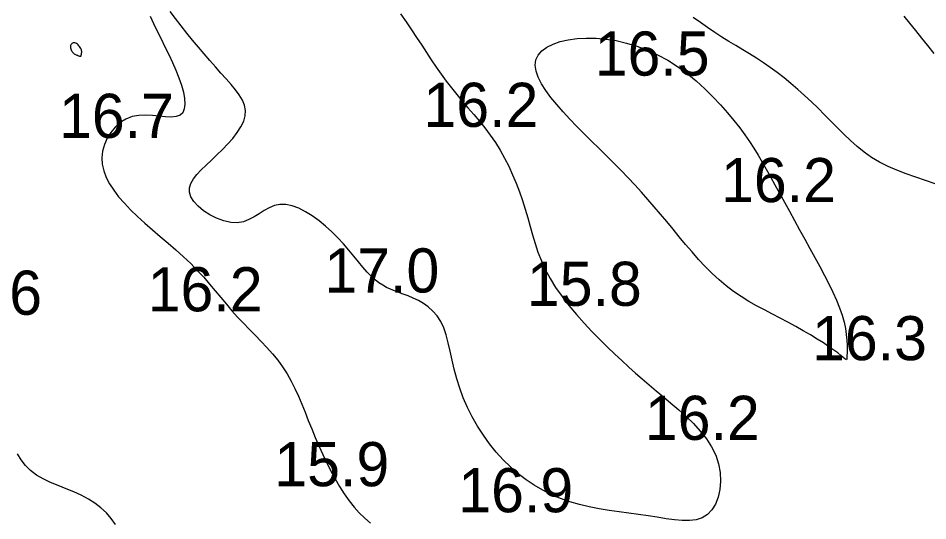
# Model space of a CAD drawing. Extents: x 3040093 to 3056816, y 408076 to 509144.
# Drawn here: x 3045566.4 to 3045669.4, y 434050.9 to 434107.9 of the extents above; entities that cross this region are included whole.
import ezdxf

# ---------------------------------------------------------------- set-up
doc = ezdxf.new("R2010")
doc.units = 0
doc.layers.add('V-CHAN-CONT-EL17', color=7, linetype='Continuous')
doc.layers.add('V-TOPO-SOUN-0610', color=7, linetype='Continuous')

msp = doc.modelspace()

# ---------------------------------------------------------------- linework, layer by layer
at = {"layer": 'V-CHAN-CONT-EL17'}
for points in [[(3045609.73, 434108.38), (3045610.36, 434107.48), (3045610.97, 434106.58), (3045611.55, 434105.7), (3045612.12, 434104.84), (3045612.67, 434103.99), (3045613.21, 434103.16), (3045613.76, 434102.34), (3045614.32, 434101.54), (3045614.89, 434100.76), (3045615.48, 434099.98), (3045616.09, 434099.23), (3045616.72, 434098.48), (3045617.36, 434097.74), (3045618.01, 434096.99), (3045618.65, 434096.23), (3045619.27, 434095.45), (3045619.88, 434094.64), (3045620.46, 434093.81), (3045621, 434092.94), (3045621.51, 434092.04), (3045621.98, 434091.1), (3045622.42, 434090.15), (3045622.83, 434089.19), (3045623.2, 434088.21), (3045623.54, 434087.23), (3045623.85, 434086.25), (3045624.13, 434085.27), (3045624.4, 434084.3), (3045624.67, 434083.32), (3045624.96, 434082.35), (3045625.29, 434081.37), (3045625.67, 434080.39), (3045626.12, 434079.39), (3045626.65, 434078.39), (3045627.29, 434077.37), (3045628.01, 434076.35), (3045628.8, 434075.33), (3045629.64, 434074.32), (3045630.51, 434073.34), (3045631.4, 434072.39), (3045632.28, 434071.48), (3045633.15, 434070.62), (3045633.98, 434069.83), (3045634.78, 434069.08), (3045635.56, 434068.36), (3045636.33, 434067.68), (3045637.1, 434067.01), (3045637.88, 434066.34), (3045638.68, 434065.67), (3045639.5, 434064.98), (3045640.35, 434064.27), (3045641.22, 434063.52), (3045642.08, 434062.75), (3045642.9, 434061.94), (3045643.67, 434061.1), (3045644.36, 434060.22), (3045644.95, 434059.31), (3045645.41, 434058.36), (3045645.74, 434057.38), (3045645.92, 434056.39), (3045645.97, 434055.41), (3045645.9, 434054.48), (3045645.71, 434053.6), (3045645.4, 434052.82), (3045644.99, 434052.16), (3045644.49, 434051.63), (3045643.89, 434051.27), (3045643.21, 434051.05), (3045642.45, 434050.96), (3045641.62, 434050.96), (3045640.73, 434051.04), (3045639.79, 434051.17), (3045638.79, 434051.33), (3045637.75, 434051.49), (3045636.68, 434051.65), (3045635.58, 434051.79), (3045634.47, 434051.94), (3045633.34, 434052.1), (3045632.21, 434052.29), (3045631.09, 434052.51), (3045629.98, 434052.77), (3045628.9, 434053.08), (3045627.84, 434053.46), (3045626.81, 434053.89), (3045625.82, 434054.39), (3045624.86, 434054.96), (3045623.94, 434055.58), (3045623.04, 434056.27), (3045622.18, 434057.03), (3045621.35, 434057.84), (3045620.56, 434058.72), (3045619.81, 434059.66), (3045619.11, 434060.64), (3045618.45, 434061.65), (3045617.85, 434062.7), (3045617.31, 434063.78), (3045616.83, 434064.86), (3045616.43, 434065.95), (3045616.09, 434067.03), (3045615.81, 434068.1), (3045615.57, 434069.15), (3045615.35, 434070.15), (3045615.13, 434071.1), (3045614.89, 434071.99), (3045614.61, 434072.8), (3045614.27, 434073.53), (3045613.86, 434074.16), (3045613.39, 434074.7), (3045612.87, 434075.16), (3045612.31, 434075.56), (3045611.74, 434075.89), (3045611.16, 434076.17), (3045610.59, 434076.41), (3045610.04, 434076.62), (3045609.53, 434076.81), (3045609.05, 434076.99), (3045608.59, 434077.18), (3045608.15, 434077.38), (3045607.71, 434077.62), (3045607.28, 434077.9), (3045606.85, 434078.23), (3045606.41, 434078.64), (3045605.94, 434079.12), (3045605.46, 434079.67), (3045604.95, 434080.28), (3045604.42, 434080.93), (3045603.86, 434081.61), (3045603.26, 434082.3), (3045602.62, 434082.99), (3045601.95, 434083.67), (3045601.24, 434084.32), (3045600.5, 434084.93), (3045599.73, 434085.48), (3045598.97, 434085.96), (3045598.2, 434086.34), (3045597.46, 434086.62), (3045596.74, 434086.78), (3045596.07, 434086.79), (3045595.44, 434086.66), (3045594.85, 434086.41), (3045594.29, 434086.09), (3045593.73, 434085.73), (3045593.16, 434085.37), (3045592.56, 434085.06), (3045591.93, 434084.82), (3045591.24, 434084.71), (3045590.49, 434084.75), (3045589.7, 434084.92), (3045588.9, 434085.22), (3045588.13, 434085.6), (3045587.42, 434086.06), (3045586.8, 434086.57), (3045586.31, 434087.1), (3045585.97, 434087.63), (3045585.81, 434088.16), (3045585.82, 434088.66), (3045585.98, 434089.17), (3045586.27, 434089.67), (3045586.67, 434090.18), (3045587.16, 434090.7), (3045587.71, 434091.24), (3045588.31, 434091.8), (3045588.93, 434092.39), (3045589.56, 434093), (3045590.17, 434093.63), (3045590.73, 434094.27), (3045591.23, 434094.92), (3045591.65, 434095.56), (3045591.96, 434096.2), (3045592.13, 434096.82), (3045592.15, 434097.43), (3045592.04, 434098.02), (3045591.81, 434098.6), (3045591.46, 434099.19), (3045591.04, 434099.78), (3045590.54, 434100.39), (3045589.98, 434101.02), (3045589.39, 434101.67), (3045588.77, 434102.36), (3045588.13, 434103.09), (3045587.48, 434103.84), (3045586.83, 434104.61), (3045586.17, 434105.4), (3045585.52, 434106.2), (3045584.87, 434107.02), (3045584.24, 434107.84), (3045583.63, 434108.66)], [(3045581.36, 434108.1), (3045581.75, 434107.27), (3045582.17, 434106.41), (3045582.61, 434105.53), (3045583.05, 434104.65), (3045583.49, 434103.76), (3045583.91, 434102.87), (3045584.29, 434101.99), (3045584.63, 434101.12), (3045584.92, 434100.29), (3045585.13, 434099.5), (3045585.26, 434098.78), (3045585.3, 434098.14), (3045585.24, 434097.6), (3045585.06, 434097.17), (3045584.75, 434096.88), (3045584.31, 434096.73), (3045583.76, 434096.68), (3045583.11, 434096.72), (3045582.4, 434096.79), (3045581.64, 434096.86), (3045580.86, 434096.9), (3045580.08, 434096.87), (3045579.33, 434096.73), (3045578.63, 434096.46), (3045577.98, 434096.05), (3045577.41, 434095.55), (3045576.91, 434094.95), (3045576.5, 434094.29), (3045576.19, 434093.58), (3045575.99, 434092.83), (3045575.91, 434092.08), (3045575.95, 434091.33), (3045576.11, 434090.59), (3045576.39, 434089.85), (3045576.77, 434089.11), (3045577.24, 434088.38), (3045577.8, 434087.64), (3045578.45, 434086.91), (3045579.16, 434086.17), (3045579.94, 434085.42), (3045580.77, 434084.67), (3045581.64, 434083.92), (3045582.52, 434083.16), (3045583.41, 434082.39), (3045584.29, 434081.62), (3045585.15, 434080.85), (3045585.96, 434080.08), (3045586.71, 434079.3), (3045587.43, 434078.53), (3045588.1, 434077.75), (3045588.75, 434076.98), (3045589.38, 434076.22), (3045590, 434075.47), (3045590.63, 434074.74), (3045591.27, 434074.02), (3045591.93, 434073.32), (3045592.59, 434072.63), (3045593.27, 434071.95), (3045593.93, 434071.26), (3045594.59, 434070.57), (3045595.21, 434069.86), (3045595.81, 434069.14), (3045596.36, 434068.38), (3045596.87, 434067.59), (3045597.33, 434066.77), (3045597.75, 434065.92), (3045598.15, 434065.05), (3045598.53, 434064.15), (3045598.91, 434063.23), (3045599.28, 434062.29), (3045599.67, 434061.34), (3045600.06, 434060.38), (3045600.48, 434059.41), (3045600.92, 434058.45), (3045601.37, 434057.5), (3045601.83, 434056.57), (3045602.32, 434055.67), (3045602.83, 434054.8), (3045603.35, 434053.98), (3045603.89, 434053.21), (3045604.46, 434052.49), (3045605.05, 434051.82), (3045605.67, 434051.22), (3045606.32, 434050.67)], [(3045670.27, 434089.13), (3045669.17, 434089.51), (3045668.07, 434089.87), (3045666.99, 434090.25), (3045665.94, 434090.65), (3045664.93, 434091.08), (3045663.97, 434091.56), (3045663.07, 434092.1), (3045662.22, 434092.7), (3045661.42, 434093.34), (3045660.66, 434094.02), (3045659.91, 434094.73), (3045659.19, 434095.46), (3045658.46, 434096.2), (3045657.74, 434096.94), (3045657, 434097.68), (3045656.25, 434098.4), (3045655.48, 434099.11), (3045654.71, 434099.8), (3045653.93, 434100.47), (3045653.15, 434101.11), (3045652.37, 434101.72), (3045651.58, 434102.29), (3045650.81, 434102.83), (3045650.03, 434103.34), (3045649.25, 434103.83), (3045648.47, 434104.3), (3045647.69, 434104.78), (3045646.9, 434105.26), (3045646.11, 434105.75), (3045645.31, 434106.28), (3045644.5, 434106.83), (3045643.69, 434107.4), (3045642.86, 434107.98)], [(3045666.73, 434108.13), (3045667.37, 434107.32), (3045668.03, 434106.49), (3045668.71, 434105.64), (3045669.4, 434104.78), (3045670.1, 434103.9)], [(3045577.45, 434050.53), (3045576.96, 434051.19), (3045576.41, 434051.82), (3045575.8, 434052.39), (3045575.12, 434052.92), (3045574.38, 434053.4), (3045573.57, 434053.82), (3045572.72, 434054.21), (3045571.84, 434054.57), (3045570.95, 434054.92), (3045570.09, 434055.29), (3045569.26, 434055.68), (3045568.5, 434056.12), (3045567.82, 434056.62), (3045567.25, 434057.2), (3045566.76, 434057.84), (3045566.34, 434058.53)]]:
    msp.add_lwpolyline(points, dxfattribs=at)
for points in [[(3045652.72, 434073.9), (3045651.83, 434074.36), (3045650.94, 434074.82), (3045650.05, 434075.3), (3045649.17, 434075.8), (3045648.3, 434076.34), (3045647.44, 434076.91), (3045646.61, 434077.54), (3045645.79, 434078.23), (3045645, 434078.97), (3045644.23, 434079.75), (3045643.48, 434080.56), (3045642.74, 434081.4), (3045642.01, 434082.26), (3045641.29, 434083.12), (3045640.58, 434083.98), (3045639.88, 434084.84), (3045639.17, 434085.68), (3045638.46, 434086.51), (3045637.74, 434087.34), (3045637.01, 434088.17), (3045636.27, 434088.99), (3045635.5, 434089.81), (3045634.71, 434090.64), (3045633.89, 434091.46), (3045633.06, 434092.29), (3045632.21, 434093.12), (3045631.36, 434093.95), (3045630.52, 434094.78), (3045629.69, 434095.61), (3045628.89, 434096.44), (3045628.13, 434097.27), (3045627.41, 434098.09), (3045626.75, 434098.9), (3045626.17, 434099.69), (3045625.68, 434100.46), (3045625.31, 434101.2), (3045625.07, 434101.9), (3045624.98, 434102.55), (3045625.06, 434103.16), (3045625.31, 434103.7), (3045625.73, 434104.18), (3045626.3, 434104.6), (3045627, 434104.95), (3045627.81, 434105.24), (3045628.72, 434105.45), (3045629.71, 434105.58), (3045630.76, 434105.64), (3045631.86, 434105.62), (3045632.99, 434105.52), (3045634.15, 434105.34), (3045635.32, 434105.07), (3045636.5, 434104.72), (3045637.68, 434104.28), (3045638.84, 434103.74), (3045639.98, 434103.12), (3045641.09, 434102.41), (3045642.17, 434101.62), (3045643.19, 434100.77), (3045644.17, 434099.89), (3045645.1, 434098.98), (3045645.96, 434098.07), (3045646.76, 434097.17), (3045647.48, 434096.3), (3045648.13, 434095.47), (3045648.71, 434094.68), (3045649.25, 434093.91), (3045649.74, 434093.15), (3045650.21, 434092.38), (3045650.67, 434091.59), (3045651.13, 434090.78), (3045651.61, 434089.92), (3045652.12, 434089.01), (3045652.65, 434088.05), (3045653.2, 434087.05), (3045653.76, 434086.02), (3045654.34, 434084.97), (3045654.92, 434083.91), (3045655.5, 434082.85), (3045656.08, 434081.79), (3045656.65, 434080.76), (3045657.21, 434079.74), (3045657.74, 434078.74), (3045658.23, 434077.78), (3045658.69, 434076.84), (3045659.1, 434075.93), (3045659.45, 434075.07), (3045659.73, 434074.24), (3045659.95, 434073.45), (3045660.1, 434072.71), (3045660.2, 434072.03), (3045660.26, 434071.4), (3045660.29, 434070.85), (3045660.29, 434070.36), (3045660.29, 434069.96), (3045660.28, 434069.64), (3045660.27, 434069.41), (3045660.26, 434069.26), (3045660.23, 434069.19), (3045660.16, 434069.21), (3045660.04, 434069.29), (3045659.86, 434069.45), (3045659.6, 434069.67), (3045659.25, 434069.95), (3045658.79, 434070.28), (3045658.24, 434070.66), (3045657.61, 434071.08), (3045656.9, 434071.53), (3045656.14, 434071.99), (3045655.32, 434072.47), (3045654.48, 434072.96), (3045653.6, 434073.43)], [(3045573.52, 434103.59), (3045573.54, 434103.61), (3045573.55, 434103.64), (3045573.56, 434103.67), (3045573.57, 434103.7), (3045573.57, 434103.75), (3045573.58, 434103.79), (3045573.59, 434103.84), (3045573.6, 434103.89), (3045573.61, 434103.95), (3045573.62, 434104), (3045573.62, 434104.07), (3045573.62, 434104.13), (3045573.61, 434104.21), (3045573.59, 434104.29), (3045573.56, 434104.38), (3045573.51, 434104.47), (3045573.45, 434104.57), (3045573.38, 434104.67), (3045573.31, 434104.77), (3045573.22, 434104.86), (3045573.13, 434104.94), (3045573.04, 434105.01), (3045572.94, 434105.05), (3045572.85, 434105.08), (3045572.75, 434105.09), (3045572.66, 434105.08), (3045572.58, 434105.05), (3045572.51, 434105), (3045572.45, 434104.95), (3045572.4, 434104.88), (3045572.36, 434104.79), (3045572.34, 434104.7), (3045572.34, 434104.61), (3045572.35, 434104.51), (3045572.38, 434104.4), (3045572.42, 434104.3), (3045572.46, 434104.2), (3045572.52, 434104.11), (3045572.57, 434104.03), (3045572.64, 434103.96), (3045572.71, 434103.9), (3045572.78, 434103.85), (3045572.85, 434103.8), (3045572.92, 434103.77), (3045572.99, 434103.73), (3045573.06, 434103.71), (3045573.13, 434103.68), (3045573.19, 434103.66), (3045573.25, 434103.63), (3045573.3, 434103.61), (3045573.35, 434103.59), (3045573.4, 434103.58), (3045573.44, 434103.57), (3045573.47, 434103.57), (3045573.5, 434103.58)]]:
    msp.add_lwpolyline(points, close=True, dxfattribs=at)

# ---------------------------------------------------------------- texts
at = {"layer": 'V-TOPO-SOUN-0610'}
for s, p in [('16.5 ', (3045631.71, 434101.38)), ('16.2 ', (3045612.32, 434095.57)), ('16.7 ', (3045571.05, 434094.32)), ('16.2 ', (3045646.02, 434087.04)), ('17.0 ', (3045601.1, 434076.8)), ('16.2 ', (3045581.09, 434074.67)), ('15.8 ', (3045624.03, 434075.29)), ('17.6 ', (3045556.12, 434074.28)), ('16.3 ', (3045656.32, 434069.13)), ('16.2 ', (3045637.39, 434060.1)), ('15.9 ', (3045595.43, 434054.85)), ('16.9 ', (3045616.26, 434051.9))]:
    msp.add_text(s, height=5, dxfattribs=at).set_placement(p)

doc.saveas('drawing.dxf')
